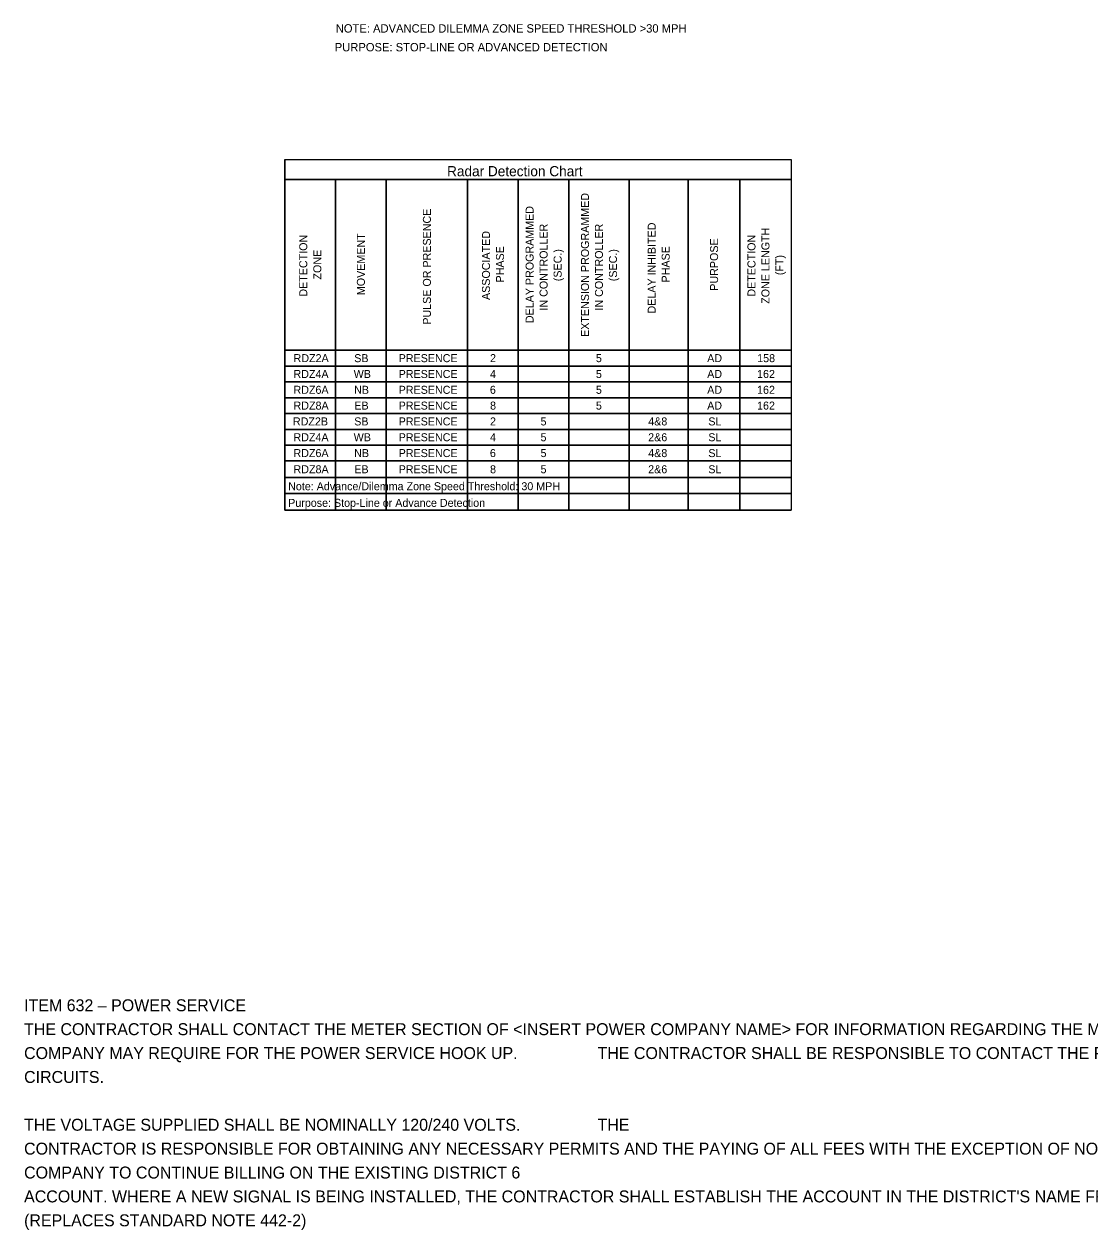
# Model space of a CAD drawing. Extents: x 22.8 to 118.4, y -49.9 to 44.8.
# Drawn here: x 75.68 to 93.52, y 2.34 to 22.52 of the extents above; entities that cross this region are included whole.
import ezdxf

# ---------------------------------------------------------------- set-up
doc = ezdxf.new("R2010")
doc.units = 0
for name, color, linetype in [('SH_Border', 7, 'Continuous'), ('SH_Text', 7, 'Continuous'), ('ST_Text', 7, 'Continuous')]:
    doc.layers.add(name, color=color, linetype=linetype)

msp = doc.modelspace()

# ---------------------------------------------------------------- linework, layer by layer
at = {"layer": 'SH_Border'}
for p, q in [((80.047, 20.254), (88.521, 20.254)), ((80.047, 20.254), (80.047, 14.389)), ((88.521, 20.254), (88.521, 14.389)), ((80.047, 19.923), (88.521, 19.923)), ((80.894, 19.923), (80.894, 14.932)), ((81.741, 19.923), (81.741, 14.932)), ((83.105, 19.923), (83.105, 14.932)), ((83.953, 19.923), (83.953, 14.932)), ((84.8, 19.923), (84.8, 14.932)), ((85.806, 19.923), (85.806, 14.932)), ((86.799, 19.923), (86.799, 14.932)), ((87.66, 19.923), (87.66, 14.932)), ((80.047, 17.063), (88.521, 17.063)), ((80.047, 16.799), (88.521, 16.799)), ((80.047, 16.534), (88.521, 16.534)), ((80.047, 16.269), (88.521, 16.269)), ((80.047, 16.004), (88.521, 16.004)), ((80.047, 15.739), (88.521, 15.739)), ((80.047, 15.475), (88.521, 15.475)), ((80.047, 15.21), (88.521, 15.21)), ((80.047, 14.932), (88.521, 14.932)), ((80.047, 14.389), (88.521, 14.389))]:
    msp.add_line(p, q, dxfattribs=at)
at = {"layer": 'SH_Text'}
for points in [[(80.047, 20.254), (88.521, 20.254), (88.521, 19.923), (80.047, 19.923)], [(80.047, 19.923), (80.894, 19.923), (80.894, 17.063), (80.047, 17.063)], [(80.894, 19.923), (81.741, 19.923), (81.741, 17.063), (80.894, 17.063)], [(81.741, 19.923), (83.105, 19.923), (83.105, 17.063), (81.741, 17.063)], [(83.105, 19.923), (83.953, 19.923), (83.953, 17.063), (83.105, 17.063)], [(83.953, 19.923), (84.8, 19.923), (84.8, 17.063), (83.953, 17.063)], [(84.8, 19.923), (85.806, 19.923), (85.806, 17.063), (84.8, 17.063)], [(85.806, 19.923), (86.799, 19.923), (86.799, 17.063), (85.806, 17.063)], [(86.799, 19.923), (87.66, 19.923), (87.66, 17.063), (86.799, 17.063)], [(87.66, 19.923), (88.521, 19.923), (88.521, 17.063), (87.66, 17.063)], [(80.047, 17.063), (80.894, 17.063), (80.894, 16.799), (80.047, 16.799)], [(80.894, 17.063), (81.741, 17.063), (81.741, 16.799), (80.894, 16.799)], [(81.741, 17.063), (83.105, 17.063), (83.105, 16.799), (81.741, 16.799)], [(83.105, 17.063), (83.953, 17.063), (83.953, 16.799), (83.105, 16.799)], [(83.953, 17.063), (84.8, 17.063), (84.8, 16.799), (83.953, 16.799)], [(84.8, 17.063), (85.806, 17.063), (85.806, 16.799), (84.8, 16.799)], [(85.806, 17.063), (86.799, 17.063), (86.799, 16.799), (85.806, 16.799)], [(86.799, 17.063), (87.66, 17.063), (87.66, 16.799), (86.799, 16.799)], [(87.66, 17.063), (88.521, 17.063), (88.521, 16.799), (87.66, 16.799)], [(80.047, 16.799), (80.894, 16.799), (80.894, 16.534), (80.047, 16.534)], [(80.894, 16.799), (81.741, 16.799), (81.741, 16.534), (80.894, 16.534)], [(81.741, 16.799), (83.105, 16.799), (83.105, 16.534), (81.741, 16.534)], [(83.105, 16.799), (83.953, 16.799), (83.953, 16.534), (83.105, 16.534)], [(83.953, 16.799), (84.8, 16.799), (84.8, 16.534), (83.953, 16.534)], [(84.8, 16.799), (85.806, 16.799), (85.806, 16.534), (84.8, 16.534)], [(85.806, 16.799), (86.799, 16.799), (86.799, 16.534), (85.806, 16.534)], [(86.799, 16.799), (87.66, 16.799), (87.66, 16.534), (86.799, 16.534)], [(87.66, 16.799), (88.521, 16.799), (88.521, 16.534), (87.66, 16.534)], [(80.047, 16.534), (80.894, 16.534), (80.894, 16.269), (80.047, 16.269)], [(80.894, 16.534), (81.741, 16.534), (81.741, 16.269), (80.894, 16.269)], [(81.741, 16.534), (83.105, 16.534), (83.105, 16.269), (81.741, 16.269)], [(83.105, 16.534), (83.953, 16.534), (83.953, 16.269), (83.105, 16.269)], [(83.953, 16.534), (84.8, 16.534), (84.8, 16.269), (83.953, 16.269)], [(84.8, 16.534), (85.806, 16.534), (85.806, 16.269), (84.8, 16.269)], [(85.806, 16.534), (86.799, 16.534), (86.799, 16.269), (85.806, 16.269)], [(86.799, 16.534), (87.66, 16.534), (87.66, 16.269), (86.799, 16.269)], [(87.66, 16.534), (88.521, 16.534), (88.521, 16.269), (87.66, 16.269)], [(80.047, 16.269), (80.894, 16.269), (80.894, 16.004), (80.047, 16.004)], [(80.894, 16.269), (81.741, 16.269), (81.741, 16.004), (80.894, 16.004)], [(81.741, 16.269), (83.105, 16.269), (83.105, 16.004), (81.741, 16.004)], [(83.105, 16.269), (83.953, 16.269), (83.953, 16.004), (83.105, 16.004)], [(83.953, 16.269), (84.8, 16.269), (84.8, 16.004), (83.953, 16.004)], [(84.8, 16.269), (85.806, 16.269), (85.806, 16.004), (84.8, 16.004)], [(85.806, 16.269), (86.799, 16.269), (86.799, 16.004), (85.806, 16.004)], [(86.799, 16.269), (87.66, 16.269), (87.66, 16.004), (86.799, 16.004)], [(87.66, 16.269), (88.521, 16.269), (88.521, 16.004), (87.66, 16.004)], [(80.047, 16.004), (80.894, 16.004), (80.894, 15.739), (80.047, 15.739)], [(80.894, 16.004), (81.741, 16.004), (81.741, 15.739), (80.894, 15.739)], [(81.741, 16.004), (83.105, 16.004), (83.105, 15.739), (81.741, 15.739)], [(83.105, 16.004), (83.953, 16.004), (83.953, 15.739), (83.105, 15.739)], [(83.953, 16.004), (84.8, 16.004), (84.8, 15.739), (83.953, 15.739)], [(84.8, 16.004), (85.806, 16.004), (85.806, 15.739), (84.8, 15.739)], [(85.806, 16.004), (86.799, 16.004), (86.799, 15.739), (85.806, 15.739)], [(86.799, 16.004), (87.66, 16.004), (87.66, 15.739), (86.799, 15.739)], [(87.66, 16.004), (88.521, 16.004), (88.521, 15.739), (87.66, 15.739)], [(80.047, 15.739), (80.894, 15.739), (80.894, 15.475), (80.047, 15.475)], [(80.894, 15.739), (81.741, 15.739), (81.741, 15.475), (80.894, 15.475)], [(81.741, 15.739), (83.105, 15.739), (83.105, 15.475), (81.741, 15.475)], [(83.105, 15.739), (83.953, 15.739), (83.953, 15.475), (83.105, 15.475)], [(83.953, 15.739), (84.8, 15.739), (84.8, 15.475), (83.953, 15.475)], [(84.8, 15.739), (85.806, 15.739), (85.806, 15.475), (84.8, 15.475)], [(85.806, 15.739), (86.799, 15.739), (86.799, 15.475), (85.806, 15.475)], [(86.799, 15.739), (87.66, 15.739), (87.66, 15.475), (86.799, 15.475)], [(87.66, 15.739), (88.521, 15.739), (88.521, 15.475), (87.66, 15.475)], [(80.047, 15.475), (80.894, 15.475), (80.894, 15.21), (80.047, 15.21)], [(80.894, 15.475), (81.741, 15.475), (81.741, 15.21), (80.894, 15.21)], [(81.741, 15.475), (83.105, 15.475), (83.105, 15.21), (81.741, 15.21)], [(83.105, 15.475), (83.953, 15.475), (83.953, 15.21), (83.105, 15.21)], [(83.953, 15.475), (84.8, 15.475), (84.8, 15.21), (83.953, 15.21)], [(84.8, 15.475), (85.806, 15.475), (85.806, 15.21), (84.8, 15.21)], [(85.806, 15.475), (86.799, 15.475), (86.799, 15.21), (85.806, 15.21)], [(86.799, 15.475), (87.66, 15.475), (87.66, 15.21), (86.799, 15.21)], [(87.66, 15.475), (88.521, 15.475), (88.521, 15.21), (87.66, 15.21)], [(80.047, 15.21), (80.894, 15.21), (80.894, 14.932), (80.047, 14.932)], [(80.894, 15.21), (81.741, 15.21), (81.741, 14.932), (80.894, 14.932)], [(81.741, 15.21), (83.105, 15.21), (83.105, 14.932), (81.741, 14.932)], [(83.105, 15.21), (83.953, 15.21), (83.953, 14.932), (83.105, 14.932)], [(83.953, 15.21), (84.8, 15.21), (84.8, 14.932), (83.953, 14.932)], [(84.8, 15.21), (85.806, 15.21), (85.806, 14.932), (84.8, 14.932)], [(85.806, 15.21), (86.799, 15.21), (86.799, 14.932), (85.806, 14.932)], [(86.799, 15.21), (87.66, 15.21), (87.66, 14.932), (86.799, 14.932)], [(87.66, 15.21), (88.521, 15.21), (88.521, 14.932), (87.66, 14.932)], [(80.047, 14.932), (80.894, 14.932), (80.894, 14.667), (80.047, 14.667)], [(80.894, 14.932), (81.741, 14.932), (81.741, 14.667), (80.894, 14.667)], [(81.741, 14.932), (83.105, 14.932), (83.105, 14.667), (81.741, 14.667)], [(83.105, 14.932), (83.953, 14.932), (83.953, 14.667), (83.105, 14.667)], [(83.953, 14.932), (84.8, 14.932), (84.8, 14.667), (83.953, 14.667)], [(84.8, 14.932), (85.806, 14.932), (85.806, 14.667), (84.8, 14.667)], [(85.806, 14.932), (86.799, 14.932), (86.799, 14.667), (85.806, 14.667)], [(86.799, 14.932), (87.66, 14.932), (87.66, 14.667), (86.799, 14.667)], [(87.66, 14.932), (88.521, 14.932), (88.521, 14.667), (87.66, 14.667)], [(80.047, 14.667), (80.894, 14.667), (80.894, 14.389), (80.047, 14.389)], [(80.894, 14.667), (81.741, 14.667), (81.741, 14.389), (80.894, 14.389)], [(81.741, 14.667), (83.105, 14.667), (83.105, 14.389), (81.741, 14.389)], [(83.105, 14.667), (83.953, 14.667), (83.953, 14.389), (83.105, 14.389)], [(83.953, 14.667), (84.8, 14.667), (84.8, 14.389), (83.953, 14.389)], [(84.8, 14.667), (85.806, 14.667), (85.806, 14.389), (84.8, 14.389)], [(85.806, 14.667), (86.799, 14.667), (86.799, 14.389), (85.806, 14.389)], [(86.799, 14.667), (87.66, 14.667), (87.66, 14.389), (86.799, 14.389)], [(87.66, 14.667), (88.521, 14.667), (88.521, 14.389), (87.66, 14.389)]]:
    msp.add_lwpolyline(points, close=True, dxfattribs=at)

# ---------------------------------------------------------------- texts
for s, height, p in [('Radar Detection Chart', 0.17054, (82.76, 19.976)), ('RDZ2A', 0.134, (80.191, 16.864)), ('SB', 0.134, (81.206, 16.864)), ('PRESENCE', 0.134, (81.95, 16.864)), ('2', 0.134, (83.479, 16.864)), ('5', 0.134, (85.252, 16.864)), ('AD', 0.134, (87.115, 16.864)), ('158', 0.134, (87.952, 16.864)), ('RDZ4A', 0.134, (80.189, 16.599)), ('WB', 0.134, (81.197, 16.599)), ('PRESENCE', 0.134, (81.95, 16.599)), ('4', 0.134, (83.479, 16.599)), ('5', 0.134, (85.252, 16.599)), ('AD', 0.134, (87.115, 16.599)), ('162', 0.134, (87.95, 16.599)), ('RDZ6A', 0.134, (80.189, 16.334)), ('NB', 0.134, (81.205, 16.334)), ('PRESENCE', 0.134, (81.95, 16.334)), ('6', 0.134, (83.477, 16.334)), ('5', 0.134, (85.252, 16.334)), ('AD', 0.134, (87.115, 16.334)), ('162', 0.134, (87.95, 16.334)), ('RDZ8A', 0.134, (80.19, 16.07)), ('EB', 0.134, (81.208, 16.07)), ('PRESENCE', 0.134, (81.95, 16.07)), ('8', 0.134, (83.48, 16.07)), ('5', 0.134, (85.252, 16.07)), ('AD', 0.134, (87.115, 16.07)), ('162', 0.134, (87.95, 16.07)), ('RDZ2B', 0.134, (80.18, 15.805)), ('SB', 0.134, (81.206, 15.805)), ('PRESENCE', 0.134, (81.95, 15.805)), ('2', 0.134, (83.479, 15.805)), ('5', 0.134, (84.325, 15.805)), ('4&8', 0.134, (86.128, 15.805)), ('SL', 0.134, (87.134, 15.805)), ('RDZ4A', 0.134, (80.189, 15.54)), ('WB', 0.134, (81.197, 15.54)), ('PRESENCE', 0.134, (81.95, 15.54)), ('4', 0.134, (83.479, 15.54)), ('5', 0.134, (84.325, 15.54)), ('2&6', 0.134, (86.127, 15.54)), ('SL', 0.134, (87.134, 15.54)), ('RDZ6A', 0.134, (80.189, 15.275)), ('NB', 0.134, (81.205, 15.275)), ('PRESENCE', 0.134, (81.95, 15.275)), ('6', 0.134, (83.477, 15.275)), ('5', 0.134, (84.325, 15.275)), ('4&8', 0.134, (86.128, 15.275)), ('SL', 0.134, (87.134, 15.275)), ('RDZ8A', 0.134, (80.19, 15.004)), ('PRESENCE', 0.134, (81.95, 15.004)), ('8', 0.134, (83.48, 15.004)), ('2&6', 0.134, (86.127, 15.004)), ('SL', 0.134, (87.134, 15.004)), ('EB', 0.134, (81.208, 15.004)), ('5', 0.134, (84.325, 15.004)), ('Note: Advance/Dilemma Zone Speed Threshold: 30 MPH', 0.134, (80.1, 14.72)), ('Purpose: Stop-Line or Advance Detection', 0.134, (80.1, 14.442)), ('ITEM 632 – POWER SERVICE', 0.2, (75.679, 5.998)), ('THE CONTRACTOR SHALL CONTACT THE METER SECTION OF <INSERT POWER COMPANY NAME> FOR INFORMATION REGARDING THE METER BASE INSTALLATION PRIOR TO ORDERING POLES. ', 0.2, (75.679, 5.598)), ('COMPANY MAY REQUIRE FOR THE POWER SERVICE HOOK UP. ', 0.2, (75.679, 5.198)), ("THE CONTRACTOR SHALL BE RESPONSIBLE TO CONTACT THE POWER COMPANY FOR THE ELECTRICAL SERVICE CONNECTION.  UNDER NO CIRCUMSTANCES SHALL THE CONTRACTROR SPLICE POWER CABLE INTO THE POWER COMPANY'S ", 0.2, (85.279, 5.198)), ('CIRCUITS. ', 0.2, (75.679, 4.798)), ('THE VOLTAGE SUPPLIED SHALL BE NOMINALLY 120/240 VOLTS. ', 0.2, (75.679, 3.998)), ('THE', 0.2, (85.279, 3.998)), ('CONTRACTOR IS RESPONSIBLE FOR OBTAINING ANY NECESSARY PERMITS AND THE PAYING OF ALL FEES WITH THE EXCEPTION OF NORMAL MONTHLY ENERGY CHARGES. WHERE THERE IS AN EXISTING TRAFFIC SIGNAL THAT IS BEING REPLACED, THE CONTRACTOR SHALL COORDINATE WITH THE POWER ', 0.2, (75.679, 3.598)), ('COMPANY TO CONTINUE BILLING ON THE EXISTING DISTRICT 6', 0.2, (75.679, 3.198)), ("ACCOUNT. WHERE A NEW SIGNAL IS BEING INSTALLED, THE CONTRACTOR SHALL ESTABLISH THE ACCOUNT IN THE DISTRICT'S NAME FROM THE ONSET.", 0.2, (75.679, 2.798)), ('(REPLACES STANDARD NOTE 442-2)', 0.2, (75.679, 2.398))]:
    msp.add_text(s, height=height, dxfattribs=at).set_placement(p)
for s, p in [('EXTENSION PROGRAMMED', (85.136, 17.287)), ('PULSE OR PRESENCE', (82.49, 17.492)), ('DELAY PROGRAMMED', (84.209, 17.517)), ('DELAY INHIBITED', (86.253, 17.678)), ('DETECTION', (80.42, 17.961)), ('MOVEMENT', (81.385, 17.986)), ('ASSOCIATED', (83.479, 17.905)), ('IN CONTROLLER', (84.443, 17.728)), ('IN CONTROLLER', (85.37, 17.728)), ('DETECTION', (87.923, 17.961)), ('ZONE LENGTH', (88.157, 17.841)), ('PHASE', (83.713, 18.198)), ('PHASE', (86.487, 18.198)), ('PURPOSE', (87.297, 18.06)), ('ZONE', (80.655, 18.247)), ('(SEC.)', (84.678, 18.219)), ('(SEC.)', (85.605, 18.219)), ('(FT)', (88.392, 18.32))]:
    msp.add_text(s, height=0.134, rotation=90, dxfattribs=at).set_placement(p)
at = {"layer": 'ST_Text'}
for s, p in [('NOTE: ADVANCED DILEMMA ZONE SPEED THRESHOLD >30 MPH', (80.897, 22.381)), ('PURPOSE: STOP-LINE OR ADVANCED DETECTION', (80.88, 22.067))]:
    msp.add_text(s, height=0.14, dxfattribs=at).set_placement(p)

doc.saveas('drawing.dxf')
